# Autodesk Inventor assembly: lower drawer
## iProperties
Created: 2005-05
Part Number: lower drawer
Document SubType Name: Assembly
Designer: a.campbell
Manufacturer: Standard
Standards Organization: Custom
B_Out_Length: 1.0 mm
B_Out_Width: 1.0 mm
B_Out_Thickness: 1.0 mm
LENGTH: 1.0 mm
WIDTH: 1.0 mm
THICKNESS: 1.0 mm
Author: a.campbell
